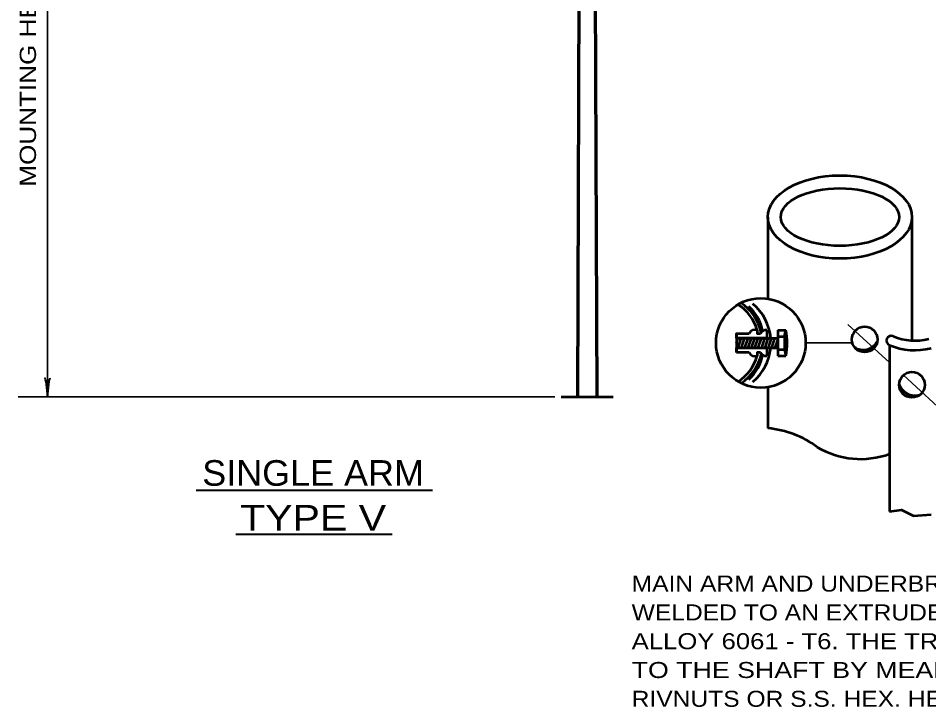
# Model space of a CAD drawing. Extents: x -20 to 693, y -19 to 435.
# Drawn here: x 200.1 to 342.4, y 212.5 to 320.5 of the extents above; entities that cross this region are included whole.
import ezdxf
from ezdxf.enums import TextEntityAlignment as Align

# ---------------------------------------------------------------- set-up
doc = ezdxf.new("R2010")
doc.units = 0
doc.layers.add('1', color=7, linetype='Continuous', lineweight=53)

msp = doc.modelspace()

# ---------------------------------------------------------------- linework, layer by layer
at = {"layer": '1', "lineweight": 35}
for p, q in [((204.677, 410.341), (204.677, 261.409)), ((329.786, 272.688), (336.286, 266.731)), ((323.174, 269.814), (330.472, 269.814)), ((338.443, 264.755), (355.108, 249.484)), ((283.957, 261.409), (200.117, 261.409))]:
    msp.add_line(p, q, dxfattribs=at)
at = {"layer": '1', "lineweight": 70}
for p, q in [((290.037, 387.409), (290.537, 261.409)), ((287.937, 372.149), (287.497, 261.409))]:
    msp.add_line(p, q, dxfattribs=at)
at = {"layer": '1'}
for p, q in [((317.286, 289.483), (317.286, 276.725)), ((339.786, 289.483), (339.786, 270.188)), ((312.352, 271.299), (312.352, 268.299)), ((312.352, 269.84), (312.588, 270.549)), ((312.352, 270.549), (318.852, 270.549)), ((312.615, 269.049), (313.115, 270.549)), ((313.142, 269.049), (313.642, 270.549)), ((313.669, 269.049), (314.169, 270.549)), ((314.197, 269.049), (314.697, 270.549)), ((314.724, 269.049), (315.224, 270.549)), ((315.251, 269.049), (315.751, 270.549)), ((315.778, 269.049), (316.278, 270.549)), ((316.305, 269.049), (316.805, 270.549)), ((316.832, 269.049), (317.332, 270.549)), ((317.359, 269.049), (317.859, 270.549)), ((317.886, 269.049), (318.386, 270.549)), ((318.413, 269.049), (318.86, 270.391)), ((318.852, 271.799), (318.852, 267.799)), ((318.852, 271.799), (320.102, 271.799)), ((318.852, 270.799), (319.852, 270.799)), ((319.852, 270.799), (320.102, 271.799)), ((319.852, 270.799), (319.852, 268.799)), ((312.352, 269.049), (318.852, 269.049)), ((336.286, 269.483), (336.286, 243.483)), ((314.352, 268.299), (312.352, 268.299)), ((318.852, 268.799), (319.852, 268.799)), ((318.852, 267.799), (320.102, 267.799)), ((319.852, 268.799), (320.102, 267.799)), ((317.286, 262.903), (317.286, 256.483)), ((284.957, 261.409), (293.077, 261.409))]:
    msp.add_line(p, q, dxfattribs=at)
at = {"layer": '1', "lineweight": 40}
for p, q in [((227.953, 246.792), (264.848, 246.792)), ((234.103, 239.952), (258.541, 239.952))]:
    msp.add_line(p, q, dxfattribs=at)
at = {"layer": '1'}
for points in [[(317.102, 271.799), (317.102, 270.549), (312.352, 270.549)], [(312.352, 270.549), (312.352, 271.299), (314.352, 271.299)], [(315.602, 271.799), (315.602, 271.299), (316.102, 271.299)], [(312.352, 268.299), (312.352, 269.049), (317.102, 269.049), (317.102, 267.799)], [(316.102, 268.299), (315.602, 268.299), (315.602, 267.799)], [(336.286, 243.483), (338.15, 243.747), (340.026, 242.808), (342.786, 242.983)]]:
    msp.add_lwpolyline(points, dxfattribs=at)
for centre, radius in [((316.174, 269.814), 7), ((332.397, 270.355), 2), ((339.79, 263.276), 2)]:
    msp.add_circle(centre, radius, dxfattribs=at)
for centre, radius, start, end in [((308.607, 269.605), 7.867, 13.93635, 55.46455), ((308.83, 269.886), 7.037, 15.77537, 57.59639), ((309.763, 270.425), 6.809, 10.53857, 48.23121), ((309.906, 269.881), 7.836, 5.00877, 50.24094), ((315.254, 270.856), 1.006, 69.78283, 153.81999), ((316.948, 270.856), 0.956, 80.76077, 152.36933), ((310.016, 269.799), 10.283, 348.78416, 11.21584), ((340.283, 278.949), 8.775, 247.10638, 284.09621), ((309.906, 269.743), 7.836, 309.75906, 354.91966), ((332.178, 271.18), 2.451, 235.7329, 330.82877), ((340.283, 278.949), 10.275, 247.10638, 284.09621), ((308.83, 269.699), 7.037, 302.69506, 344.35053), ((308.604, 269.982), 7.894, 304.95191, 346.02256), ((309.763, 269.2), 6.809, 311.76879, 349.22077), ((315.254, 268.743), 1.006, 206.18001, 290.21717), ((316.948, 268.742), 0.956, 207.63067, 279.23923), ((340.302, 264.293), 2.701, 201.59386, 285.00235), ((315.829, 241.072), 15.48, 53.68055, 84.60091), ((331.747, 264.772), 13.1, 238.98613, 290.27051)]:
    msp.add_arc(centre, radius, start, end, dxfattribs=at)
for major_axis, ratio in [((11.25, 0), 0.577778), ((9.25, 0), 0.486486)]:
    msp.add_ellipse((328.536, 289.483), major_axis=major_axis, ratio=ratio, dxfattribs=at)
msp.add_ellipse((336.578, 270.174), major_axis=(-0.732, 0.309), ratio=0.94369, start_param=4.712389, end_param=7.8539816, dxfattribs=at)
at = {"layer": '1', "lineweight": 40}
for centre, major_axis, ratio, start_param, end_param in [((204.403, 262.508), (0.159, -1.814), 0.122415, 0.8963533, 3.1415927), ((204.403, 262.508), (0.159, -1.814), 0.122415, 0.8963533, 3.1415927), ((204.898, 262.538), (0.178, 1.785), 0.07063, 6.2823074, 8.5597026), ((204.898, 262.538), (0.178, 1.785), 0.07063, 6.2823074, 8.5597026)]:
    msp.add_ellipse(centre, major_axis=major_axis, ratio=ratio, start_param=start_param, end_param=end_param, dxfattribs=at)

# ---------------------------------------------------------------- texts
at = {"layer": '1', "width": 1.2}
msp.add_text('MOUNTING HEIGHT 7.6m THROUGH 15.2m', height=2.54, rotation=90, dxfattribs=at).set_placement((202.894, 294.227))
at = {"layer": '1'}
for s, width, p in [('SINGLE ARM', 1.05, (246.2, 247.494)), ('TYPE V', 1.2, (246.2, 240.494))]:
    msp.add_text(s, height=4, dxfattribs=dict(at, width=width)).set_placement(p, align=Align.CENTER)
for s, width, p in [('MAIN ARM AND UNDERBRACE (AS APPLICABLE) IS', 1.15, (295.986, 230.956)), ('WELDED TO AN EXTRUDED MOUNTING PLATE OF', 1.15, (295.986, 226.456)), ('ALLOY 6061 - T6. THE TRUSS ARM(S) IS ASSEMBLED', 1.2, (295.986, 221.956)), ('TO THE SHAFT BY MEANS OF FOUR, SIX OR EIGHT', 1.25, (295.986, 217.456)), ('RIVNUTS OR S.S. HEX. HEAD BOLTS, DEPENDING', 1.15, (295.986, 212.956))]:
    msp.add_text(s, height=2.5, dxfattribs=dict(at, width=width)).set_placement(p)

doc.saveas('drawing.dxf')
